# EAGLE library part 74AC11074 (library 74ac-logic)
Dual positive edge triggered D-type FLIP FLOP
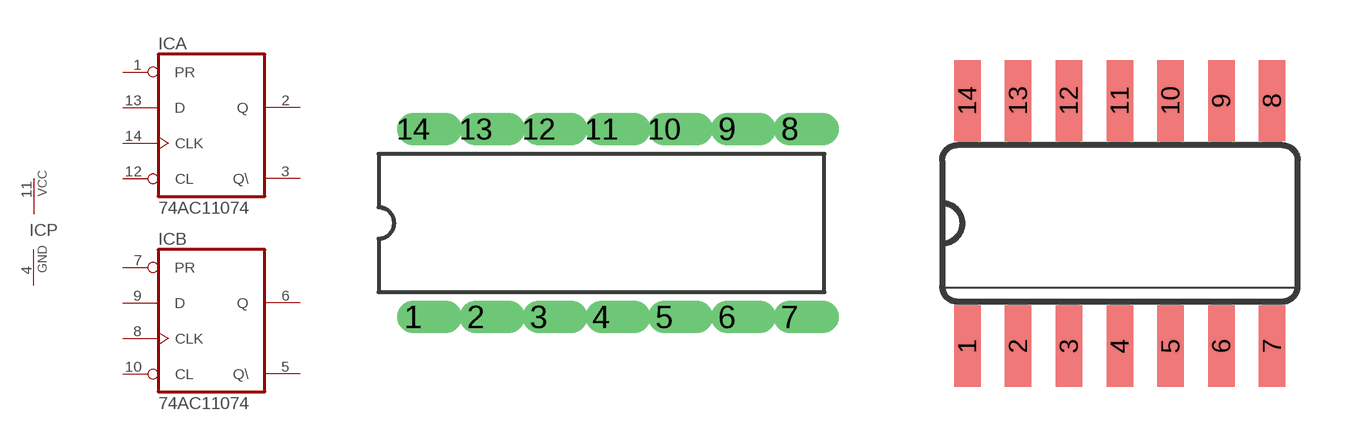
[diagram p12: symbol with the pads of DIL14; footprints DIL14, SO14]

Designator prefix IC; gates A=7411074 B=7411074 P=PWRN

## 74AC11074  [DIL14]
1  A:PR  in
2  A:Q  out
3  A:Q\  out
4  P:GND  pwr
5  B:Q\  out
6  B:Q  out
7  B:PR  in
8  B:CLK  in
9  B:D  in
10  B:CL  in
11  P:VCC  pwr
12  A:CL  in
13  A:D  in
14  A:CLK  in

## 74AC11074D  [SO14]
Pads as for DIL14

## Footprint DIL14 (pad centres in mm)
Dual In Line
drill 0.813 offset: 1 -7.62,-3.81; 2 -5.08,-3.81; 3 -2.54,-3.81; 4 0,-3.81; 5 2.54,-3.81; 6 5.08,-3.81; 7 7.62,-3.81; 8 7.62,3.81; 9 5.08,3.81; 10 2.54,3.81; 11 0,3.81; 12 -2.54,3.81; 13 -5.08,3.81; 14 -7.62,3.81

## Footprint SO14 (pad centres in mm)
Small Outline package 150 mil
smd 0.66 x 2.032: 1 -3.81,-3.073; 2 -2.54,-3.073; 3 -1.27,-3.073; 4 0,-3.073; 5 1.27,-3.073; 6 2.54,-3.073; 7 3.81,-3.073; 8 3.81,3.073; 9 2.54,3.073; 10 1.27,3.073; 11 0,3.073; 12 -1.27,3.073; 13 -2.54,3.073; 14 -3.81,3.073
